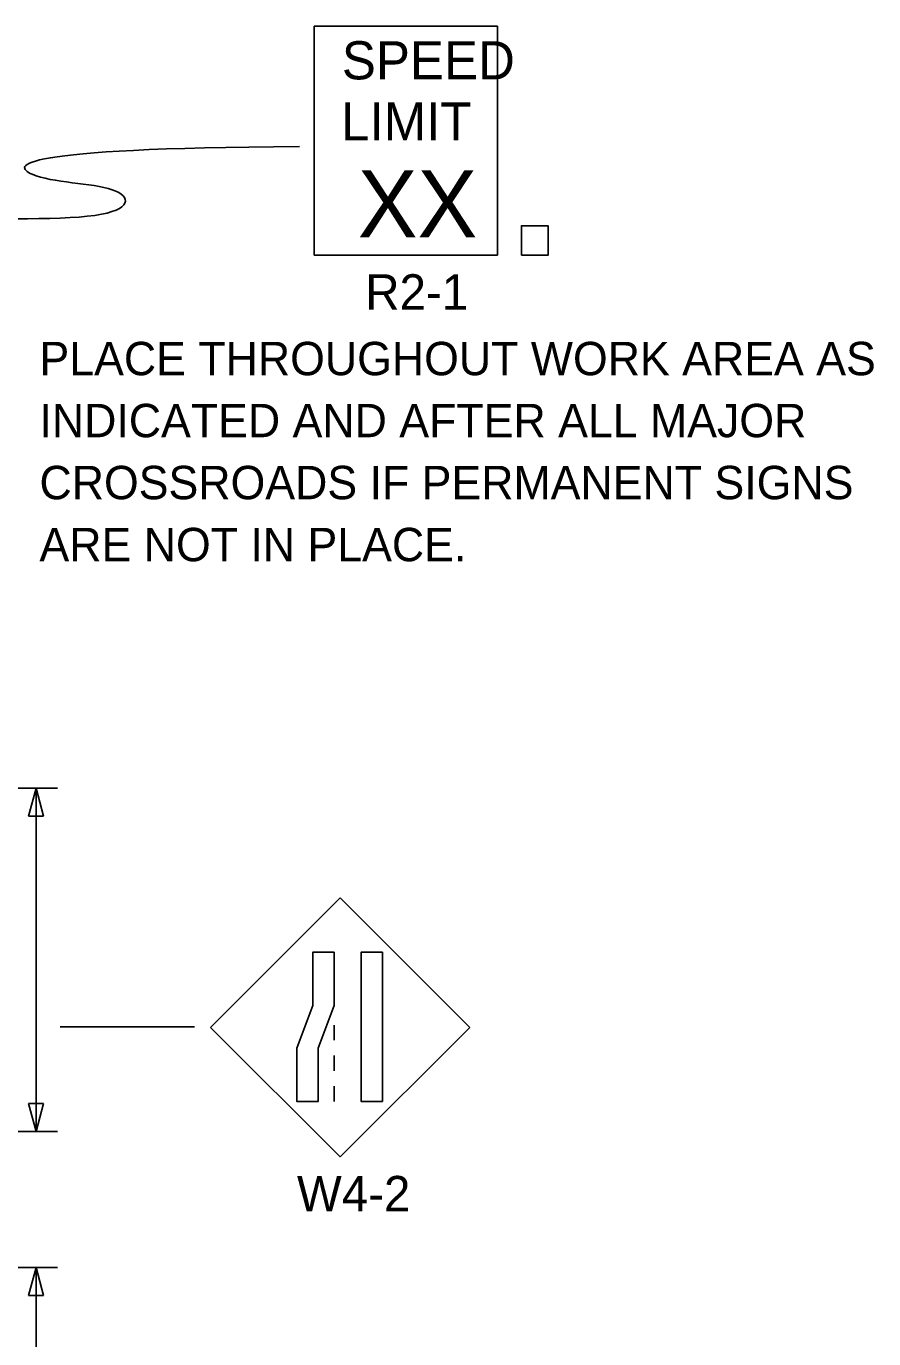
# Model space of a CAD drawing. Extents: x 16731 to 18475, y 7003 to 8262.
# Drawn here: x 17202 to 17379.6, y 7661 to 7936.2 of the extents above; entities that cross this region are included whole.
import ezdxf

# ---------------------------------------------------------------- set-up
doc = ezdxf.new("R2010")
doc.units = 0
doc.layers.add('TRAFFIC_SIGNS_PR', color=7, linetype='Continuous')
doc.layers.add('TYPICAL_TEXT_DIMEN_PR', color=7, linetype='Continuous')

msp = doc.modelspace()

# ---------------------------------------------------------------- linework, layer by layer
at = {"layer": 'TRAFFIC_SIGNS_PR'}
for p, q in [((17262.39, 7936.17), (17300.79, 7936.17)), ((17262.39, 7888.17), (17262.39, 7936.17)), ((17300.79, 7888.17), (17300.79, 7936.17)), ((17262.39, 7888.17), (17300.79, 7888.17)), ((17267.79, 7753.41), (17240.64, 7726.26)), ((17294.95, 7726.26), (17267.79, 7753.41)), ((17240.64, 7726.26), (17267.79, 7699.11)), ((17266.55, 7726.75), (17266.55, 7723.55)), ((17267.79, 7699.11), (17294.95, 7726.26)), ((17266.55, 7720.35), (17266.55, 7717.15)), ((17266.55, 7713.95), (17266.55, 7710.75))]:
    msp.add_line(p, q, dxfattribs=at)
for points in [[(17305.81, 7888.17), (17311.4, 7888.17), (17311.4, 7894.34), (17305.81, 7894.34)], [(17266.55, 7742), (17266.55, 7730.82), (17263.2, 7721.93), (17263.2, 7710.75), (17258.71, 7710.75), (17258.71, 7721.93), (17262.05, 7730.82), (17262.05, 7742)], [(17276.68, 7742), (17276.68, 7710.75), (17272.19, 7710.75), (17272.19, 7742)]]:
    msp.add_lwpolyline(points, close=True, dxfattribs=at)
at = {"layer": 'TYPICAL_TEXT_DIMEN_PR'}
for p, q in [((17208.6, 7776.39), (17072.6, 7776.39)), ((17202.52, 7770.53), (17204.09, 7776.39)), ((17204.09, 7776.39), (17204.09, 7704.4)), ((17204.09, 7776.39), (17205.66, 7770.53)), ((17204.09, 7770.53), (17202.52, 7770.53)), ((17205.66, 7770.53), (17204.09, 7770.53)), ((17209.14, 7726.39), (17237.27, 7726.39)), ((17204.09, 7704.4), (17202.52, 7710.27)), ((17202.52, 7710.27), (17204.09, 7710.27)), ((17204.09, 7710.27), (17205.66, 7710.27)), ((17205.66, 7710.27), (17204.09, 7704.4)), ((17208.6, 7704.4), (17072.6, 7704.4)), ((17208.6, 7675.89), (17049.19, 7675.89)), ((17202.52, 7670.03), (17204.09, 7675.89)), ((17204.09, 7675.89), (17205.66, 7670.03)), ((17204.09, 7675.89), (17204.09, 7625.89)), ((17204.09, 7670.03), (17202.52, 7670.03)), ((17205.66, 7670.03), (17204.09, 7670.03))]:
    msp.add_line(p, q, dxfattribs=at)
msp.add_open_spline([(17259.28, 7910.95), (17199.04, 7910.59), (17199.04, 7903.32), (17224.22, 7903.32), (17224.22, 7894.79), (17192.85, 7895.99), (17177.35, 7895.57)], degree=3, dxfattribs=at)

# ---------------------------------------------------------------- texts
at = {"layer": 'TRAFFIC_SIGNS_PR'}
for s, height, p in [('SPEED', 8, (17268.16, 7925.03)), ('LIMIT', 8, (17268, 7912.23)), ('XX', 14.031, (17271.5, 7891.93)), ('R2-1', 7.44, (17273.07, 7876.73)), ('PLACE THROUGHOUT WORK AREA AS', 7, (17204.79, 7863)), ('INDICATED AND AFTER ALL MAJOR', 7, (17204.79, 7850)), ('CROSSROADS IF PERMANENT SIGNS', 7, (17204.79, 7837)), ('ARE NOT IN PLACE.', 7, (17204.79, 7824)), ('W4-2', 7.44, (17258.75, 7687.67))]:
    msp.add_text(s, height=height, dxfattribs=at).set_placement(p)

doc.saveas('drawing.dxf')
